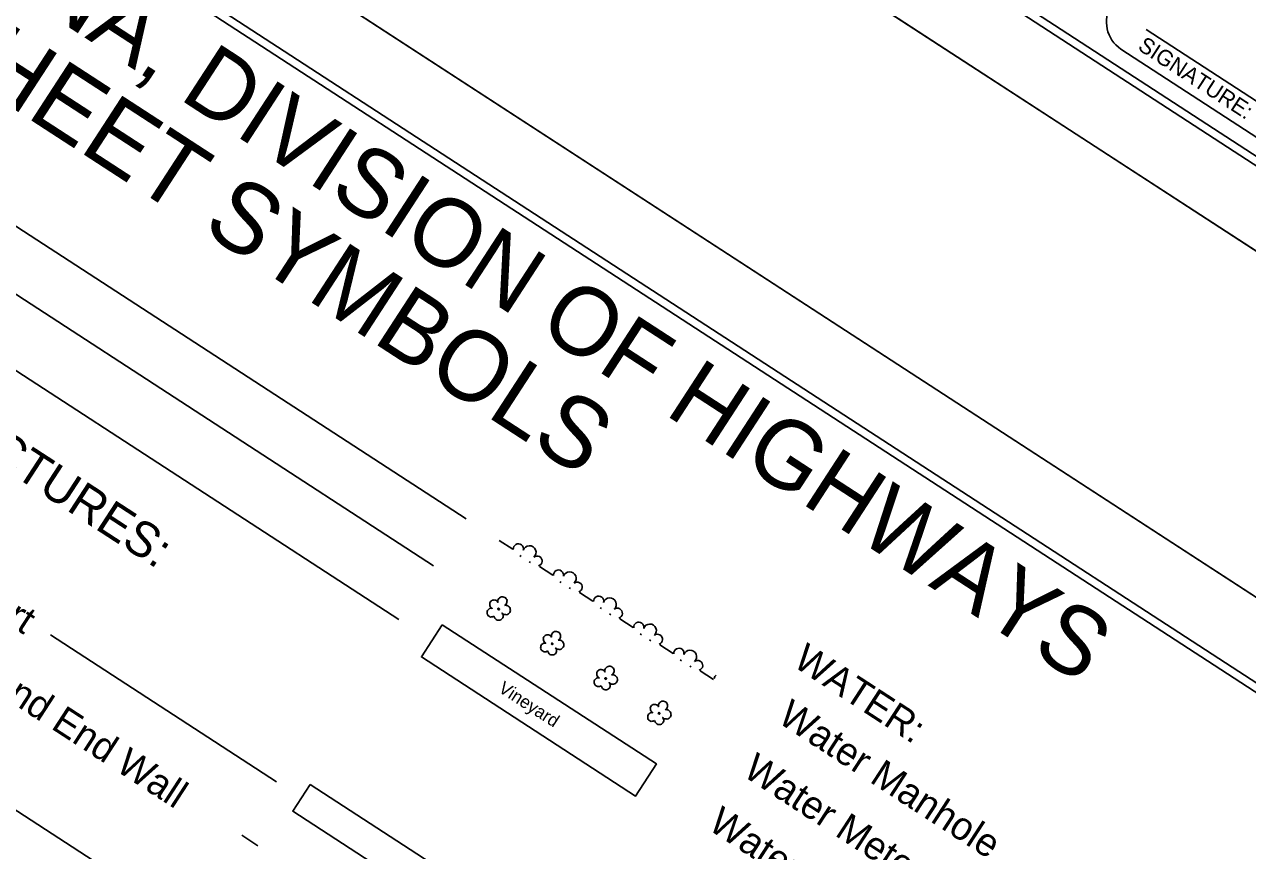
# Model space of a CAD drawing. Extents: x 2291197 to 2302790, y 592892 to 604246.
# Drawn here: x 2296768 to 2298300, y 596869 to 597905 of the extents above; entities that cross this region are included whole.
import ezdxf

# ---------------------------------------------------------------- set-up
doc = ezdxf.new("R2010")
doc.units = 0
for name, color, linetype in [('Prop Shade Light', 7, 'Continuous'), ('Sheet Cutting Line CELL', 7, 'Continuous'), ('Sheet Plot Border Inside CELL', 7, 'Continuous'), ('Sheet Plot Border Outside CELL', 7, 'Continuous'), ('Sheet Symbology CELL', 7, 'Continuous'), ('Sheet Title CELL', 7, 'Continuous')]:
    doc.layers.add(name, color=color, linetype=linetype)

# ---------------------------------------------------------------- blocks, each defined once
blk = doc.blocks.new('PLAN SHEET SYMBOLOGY - New')
at = {"layer": 'Sheet Cutting Line CELL'}
blk.add_line((1439376.56, 921733.15), (1437692.56, 921733.15), dxfattribs=at)
at = {"layer": 'Sheet Plot Border Inside CELL'}
blk.add_lwpolyline([(1437705.56, 920655.6), (1439372.06, 920655.6), (1439372.06, 921710.7), (1437705.56, 921710.7)], close=True, dxfattribs=at)
at = {"layer": 'Sheet Plot Border Outside CELL'}
blk.add_lwpolyline([(1437692.56, 920633.15), (1439376.56, 920633.15), (1439376.56, 921733.15), (1437692.56, 921733.15)], close=True, dxfattribs=at)
at = {"layer": 'Sheet Symbology CELL'}
for p, q in [((1438877.82, 921618.88), (1438696.7, 921618.88)), ((1438890.21, 921618.88), (1438895.21, 921618.88)), ((1438898.16, 921618.38), (1438898.66, 921618.38)), ((1438901.66, 921618.38), (1438902.16, 921618.38)), ((1438905.21, 921618.88), (1438910.21, 921618.88)), ((1438913.16, 921618.38), (1438913.66, 921618.38)), ((1438916.66, 921618.38), (1438917.16, 921618.38)), ((1438920.21, 921618.88), (1438925.21, 921618.88)), ((1438928.16, 921618.38), (1438928.66, 921618.38)), ((1438931.66, 921618.38), (1438932.16, 921618.38)), ((1438935.21, 921618.88), (1438940.21, 921618.88)), ((1438943.16, 921618.38), (1438943.66, 921618.38)), ((1438946.66, 921618.38), (1438947.16, 921618.38)), ((1438950.21, 921618.88), (1438955.21, 921618.88)), ((1438958.16, 921618.38), (1438958.66, 921618.38)), ((1438961.66, 921618.38), (1438962.16, 921618.38)), ((1438965.21, 921618.88), (1438970.21, 921618.88)), ((1438877.26, 921600.96), (1438672.32, 921600.96)), ((1438877.26, 921580.96), (1438672.32, 921580.96)), ((1438872.94, 921517.45), (1438788.52, 921517.45)), ((1438872.94, 921497.45), (1438878.93, 921497.45)), ((1438872.94, 921465.46), (1438744.64, 921465.46))]:
    blk.add_line(p, q, dxfattribs=at)
blk.add_lwpolyline([(1439359.56, 921708.15), (1437859.56, 921708.15), (1437859.56, 920659.17), (1439359.56, 920659.17)], close=True, dxfattribs=at)
for points in [[(1438902.7, 921602.71), (1438902.85, 921603.01), (1438902.9, 921603.31), (1438902.85, 921603.61), (1438902.8, 921603.91), (1438902.65, 921604.16), (1438902.5, 921604.41), (1438902.25, 921604.61), (1438902, 921604.76), (1438901.65, 921604.86), (1438901.4, 921604.86), (1438901.1, 921604.81), (1438900.8, 921604.71), (1438900.55, 921604.56), (1438900.3, 921604.36), (1438900.15, 921604.06), (1438900.05, 921603.81), (1438900, 921603.51), (1438900, 921603.21), (1438900.05, 921602.91), (1438900.2, 921602.66), (1438900.4, 921602.36), (1438900.15, 921602.51), (1438899.85, 921602.56), (1438899.55, 921602.56), (1438899.3, 921602.46), (1438899.05, 921602.36), (1438898.8, 921602.16), (1438898.6, 921601.96), (1438898.45, 921601.71), (1438898.4, 921601.46), (1438898.35, 921601.11), (1438898.4, 921600.86), (1438898.5, 921600.61), (1438898.7, 921600.36), (1438898.85, 921600.16), (1438899.1, 921600.01), (1438899.4, 921599.86), (1438899.65, 921599.81), (1438899.95, 921599.81), (1438899.7, 921599.71), (1438899.45, 921599.51), (1438899.3, 921599.31), (1438899.2, 921599.01), (1438899.1, 921598.71), (1438899.1, 921598.46), (1438899.15, 921598.16), (1438899.3, 921597.91), (1438899.45, 921597.66), (1438899.65, 921597.46), (1438899.9, 921597.31), (1438900.15, 921597.21), (1438900.45, 921597.21), (1438900.75, 921597.21), (1438901, 921597.26), (1438901.25, 921597.46), (1438901.5, 921597.61), (1438901.75, 921598.06)], [(1438922.7, 921602.71), (1438922.85, 921603.01), (1438922.9, 921603.31), (1438922.85, 921603.61), (1438922.8, 921603.91), (1438922.65, 921604.16), (1438922.5, 921604.41), (1438922.25, 921604.61), (1438922, 921604.76), (1438921.65, 921604.86), (1438921.4, 921604.86), (1438921.1, 921604.81), (1438920.8, 921604.71), (1438920.55, 921604.56), (1438920.3, 921604.36), (1438920.15, 921604.06), (1438920.05, 921603.81), (1438920, 921603.51), (1438920, 921603.21), (1438920.05, 921602.91), (1438920.2, 921602.66), (1438920.4, 921602.36), (1438920.15, 921602.51), (1438919.85, 921602.56), (1438919.55, 921602.56), (1438919.3, 921602.46), (1438919.05, 921602.36), (1438918.8, 921602.16), (1438918.6, 921601.96), (1438918.45, 921601.71), (1438918.4, 921601.46), (1438918.35, 921601.11), (1438918.4, 921600.86), (1438918.5, 921600.61), (1438918.7, 921600.36), (1438918.85, 921600.16), (1438919.1, 921600.01), (1438919.4, 921599.86), (1438919.65, 921599.81), (1438919.95, 921599.81), (1438919.7, 921599.71), (1438919.45, 921599.51), (1438919.3, 921599.31), (1438919.2, 921599.01), (1438919.1, 921598.71), (1438919.1, 921598.46), (1438919.15, 921598.16), (1438919.3, 921597.91), (1438919.45, 921597.66), (1438919.65, 921597.46), (1438919.9, 921597.31), (1438920.15, 921597.21), (1438920.45, 921597.21), (1438920.75, 921597.21), (1438921, 921597.26), (1438921.25, 921597.46), (1438921.5, 921597.61), (1438921.75, 921598.06)], [(1438942.7, 921602.71), (1438942.85, 921603.01), (1438942.9, 921603.31), (1438942.85, 921603.61), (1438942.8, 921603.91), (1438942.65, 921604.16), (1438942.5, 921604.41), (1438942.25, 921604.61), (1438942, 921604.76), (1438941.65, 921604.86), (1438941.4, 921604.86), (1438941.1, 921604.81), (1438940.8, 921604.71), (1438940.55, 921604.56), (1438940.3, 921604.36), (1438940.15, 921604.06), (1438940.05, 921603.81), (1438940, 921603.51), (1438940, 921603.21), (1438940.05, 921602.91), (1438940.2, 921602.66), (1438940.4, 921602.36), (1438940.15, 921602.51), (1438939.85, 921602.56), (1438939.55, 921602.56), (1438939.3, 921602.46), (1438939.05, 921602.36), (1438938.8, 921602.16), (1438938.6, 921601.96), (1438938.45, 921601.71), (1438938.4, 921601.46), (1438938.35, 921601.11), (1438938.4, 921600.86), (1438938.5, 921600.61), (1438938.7, 921600.36), (1438938.85, 921600.16), (1438939.1, 921600.01), (1438939.4, 921599.86), (1438939.65, 921599.81), (1438939.95, 921599.81), (1438939.7, 921599.71), (1438939.45, 921599.51), (1438939.3, 921599.31), (1438939.2, 921599.01), (1438939.1, 921598.71), (1438939.1, 921598.46), (1438939.15, 921598.16), (1438939.3, 921597.91), (1438939.45, 921597.66), (1438939.65, 921597.46), (1438939.9, 921597.31), (1438940.15, 921597.21), (1438940.45, 921597.21), (1438940.75, 921597.21), (1438941, 921597.26), (1438941.25, 921597.46), (1438941.5, 921597.61), (1438941.75, 921598.06)], [(1438962.7, 921602.71), (1438962.85, 921603.01), (1438962.9, 921603.31), (1438962.85, 921603.61), (1438962.8, 921603.91), (1438962.65, 921604.16), (1438962.5, 921604.41), (1438962.25, 921604.61), (1438962, 921604.76), (1438961.65, 921604.86), (1438961.4, 921604.86), (1438961.1, 921604.81), (1438960.8, 921604.71), (1438960.55, 921604.56), (1438960.3, 921604.36), (1438960.15, 921604.06), (1438960.05, 921603.81), (1438960, 921603.51), (1438960, 921603.21), (1438960.05, 921602.91), (1438960.2, 921602.66), (1438960.4, 921602.36), (1438960.15, 921602.51), (1438959.85, 921602.56), (1438959.55, 921602.56), (1438959.3, 921602.46), (1438959.05, 921602.36), (1438958.8, 921602.16), (1438958.6, 921601.96), (1438958.45, 921601.71), (1438958.4, 921601.46), (1438958.35, 921601.11), (1438958.4, 921600.86), (1438958.5, 921600.61), (1438958.7, 921600.36), (1438958.85, 921600.16), (1438959.1, 921600.01), (1438959.4, 921599.86), (1438959.65, 921599.81), (1438959.95, 921599.81), (1438959.7, 921599.71), (1438959.45, 921599.51), (1438959.3, 921599.31), (1438959.2, 921599.01), (1438959.1, 921598.71), (1438959.1, 921598.46), (1438959.15, 921598.16), (1438959.3, 921597.91), (1438959.45, 921597.66), (1438959.65, 921597.46), (1438959.9, 921597.31), (1438960.15, 921597.21), (1438960.45, 921597.21), (1438960.75, 921597.21), (1438961, 921597.26), (1438961.25, 921597.46), (1438961.5, 921597.61), (1438961.75, 921598.06)], [(1438901.85, 921600.96), (1438901.7, 921600.96), (1438901.6, 921600.91), (1438901.5, 921600.86), (1438901.5, 921600.71), (1438901.5, 921600.61), (1438901.6, 921600.51), (1438901.75, 921600.51), (1438901.85, 921600.51), (1438901.95, 921600.61), (1438902, 921600.76), (1438901.95, 921600.86), (1438901.85, 921600.96)], [(1438901.75, 921598.06), (1438902.35, 921597.71), (1438902.65, 921597.61), (1438902.95, 921597.56), (1438903.25, 921597.61), (1438903.5, 921597.71), (1438903.75, 921597.86), (1438904, 921598.06), (1438904.15, 921598.31), (1438904.25, 921598.56), (1438904.35, 921598.86), (1438904.3, 921599.16), (1438904.25, 921599.46), (1438904.05, 921599.76), (1438903.9, 921599.96), (1438903.65, 921600.11), (1438903.35, 921600.26), (1438903.65, 921600.21), (1438904, 921600.21), (1438904.25, 921600.31), (1438904.55, 921600.46), (1438904.8, 921600.61), (1438905, 921600.86), (1438905.15, 921601.16), (1438905.2, 921601.46), (1438905.25, 921601.76), (1438905.2, 921602.06), (1438905.1, 921602.36), (1438904.9, 921602.61), (1438904.65, 921602.86), (1438904.4, 921603.01), (1438904.1, 921603.11), (1438903.8, 921603.16), (1438903.5, 921603.16), (1438903.2, 921603.06), (1438902.95, 921602.91), (1438902.7, 921602.71)], [(1438921.85, 921600.96), (1438921.7, 921600.96), (1438921.6, 921600.91), (1438921.5, 921600.86), (1438921.5, 921600.71), (1438921.5, 921600.61), (1438921.6, 921600.51), (1438921.75, 921600.51), (1438921.85, 921600.51), (1438921.95, 921600.61), (1438922, 921600.76), (1438921.95, 921600.86), (1438921.85, 921600.96)], [(1438921.75, 921598.06), (1438922.35, 921597.71), (1438922.65, 921597.61), (1438922.95, 921597.56), (1438923.25, 921597.61), (1438923.5, 921597.71), (1438923.75, 921597.86), (1438924, 921598.06), (1438924.15, 921598.31), (1438924.25, 921598.56), (1438924.35, 921598.86), (1438924.3, 921599.16), (1438924.25, 921599.46), (1438924.05, 921599.76), (1438923.9, 921599.96), (1438923.65, 921600.11), (1438923.35, 921600.26), (1438923.65, 921600.21), (1438924, 921600.21), (1438924.25, 921600.31), (1438924.55, 921600.46), (1438924.8, 921600.61), (1438925, 921600.86), (1438925.15, 921601.16), (1438925.2, 921601.46), (1438925.25, 921601.76), (1438925.2, 921602.06), (1438925.1, 921602.36), (1438924.9, 921602.61), (1438924.65, 921602.86), (1438924.4, 921603.01), (1438924.1, 921603.11), (1438923.8, 921603.16), (1438923.5, 921603.16), (1438923.2, 921603.06), (1438922.95, 921602.91), (1438922.7, 921602.71)], [(1438941.85, 921600.96), (1438941.7, 921600.96), (1438941.6, 921600.91), (1438941.5, 921600.86), (1438941.5, 921600.71), (1438941.5, 921600.61), (1438941.6, 921600.51), (1438941.75, 921600.51), (1438941.85, 921600.51), (1438941.95, 921600.61), (1438942, 921600.76), (1438941.95, 921600.86), (1438941.85, 921600.96)], [(1438941.75, 921598.06), (1438942.35, 921597.71), (1438942.65, 921597.61), (1438942.95, 921597.56), (1438943.25, 921597.61), (1438943.5, 921597.71), (1438943.75, 921597.86), (1438944, 921598.06), (1438944.15, 921598.31), (1438944.25, 921598.56), (1438944.35, 921598.86), (1438944.3, 921599.16), (1438944.25, 921599.46), (1438944.05, 921599.76), (1438943.9, 921599.96), (1438943.65, 921600.11), (1438943.35, 921600.26), (1438943.65, 921600.21), (1438944, 921600.21), (1438944.25, 921600.31), (1438944.55, 921600.46), (1438944.8, 921600.61), (1438945, 921600.86), (1438945.15, 921601.16), (1438945.2, 921601.46), (1438945.25, 921601.76), (1438945.2, 921602.06), (1438945.1, 921602.36), (1438944.9, 921602.61), (1438944.65, 921602.86), (1438944.4, 921603.01), (1438944.1, 921603.11), (1438943.8, 921603.16), (1438943.5, 921603.16), (1438943.2, 921603.06), (1438942.95, 921602.91), (1438942.7, 921602.71)], [(1438961.85, 921600.96), (1438961.7, 921600.96), (1438961.6, 921600.91), (1438961.5, 921600.86), (1438961.5, 921600.71), (1438961.5, 921600.61), (1438961.6, 921600.51), (1438961.75, 921600.51), (1438961.85, 921600.51), (1438961.95, 921600.61), (1438962, 921600.76), (1438961.95, 921600.86), (1438961.85, 921600.96)], [(1438961.75, 921598.06), (1438962.35, 921597.71), (1438962.65, 921597.61), (1438962.95, 921597.56), (1438963.25, 921597.61), (1438963.5, 921597.71), (1438963.75, 921597.86), (1438964, 921598.06), (1438964.15, 921598.31), (1438964.25, 921598.56), (1438964.35, 921598.86), (1438964.3, 921599.16), (1438964.25, 921599.46), (1438964.05, 921599.76), (1438963.9, 921599.96), (1438963.65, 921600.11), (1438963.35, 921600.26), (1438963.65, 921600.21), (1438964, 921600.21), (1438964.25, 921600.31), (1438964.55, 921600.46), (1438964.8, 921600.61), (1438965, 921600.86), (1438965.15, 921601.16), (1438965.2, 921601.46), (1438965.25, 921601.76), (1438965.2, 921602.06), (1438965.1, 921602.36), (1438964.9, 921602.61), (1438964.65, 921602.86), (1438964.4, 921603.01), (1438964.1, 921603.11), (1438963.8, 921603.16), (1438963.5, 921603.16), (1438963.2, 921603.06), (1438962.95, 921602.91), (1438962.7, 921602.71)], [(1438889.65, 921586.96), (1438969.65, 921586.96), (1438969.65, 921574.96), (1438889.65, 921574.96), (1438889.65, 921586.96)], [(1438882.24, 921522.45), (1438964.74, 921522.45), (1438964.74, 921512.45), (1438882.24, 921512.45), (1438882.24, 921522.45)]]:
    blk.add_lwpolyline(points, dxfattribs=at)
for centre, radius, start, end in [((1438896.66, 921619.9), 1.58, 18.435, 219.2315), ((1438900.16, 921620.9), 2.06, 345.9638, 194.0362), ((1438903.66, 921619.9), 1.58, 320.7685, 161.5651), ((1438911.66, 921619.9), 1.58, 18.435, 219.2315), ((1438915.16, 921620.9), 2.06, 345.9638, 194.0362), ((1438918.66, 921619.9), 1.58, 320.7685, 161.5651), ((1438926.66, 921619.9), 1.58, 18.435, 219.2315), ((1438930.16, 921620.9), 2.06, 345.9638, 194.0362), ((1438933.66, 921619.9), 1.58, 320.7685, 161.5651), ((1438941.66, 921619.9), 1.58, 18.435, 219.2315), ((1438945.16, 921620.9), 2.06, 345.9638, 194.0362), ((1438948.66, 921619.9), 1.58, 320.7685, 161.5651), ((1438956.66, 921619.9), 1.58, 18.435, 219.2315), ((1438960.16, 921620.9), 2.06, 345.9638, 194.0362), ((1438963.66, 921619.9), 1.58, 320.7685, 161.5651), ((1438971.66, 921619.9), 1.58, 156.251, 203.749)]:
    blk.add_arc(centre, radius, start, end, dxfattribs=at)
for s, height, p in [('STATE OF NORTH CAROLINA, DIVISION OF HIGHWAYS', 21.419, (1438310.12, 921680.19)), ('CONVENTIONAL  PLAN SHEET SYMBOLS', 22.0323, (1438318.25, 921649.31)), ('WATER:', 8.75, (1438988.35, 921635.98)), ('Water Manhole', 8.75, (1438993.92, 921618.6)), ('Water Meter', 8.75, (1438993.92, 921598.6)), ('Water Valve', 8.75, (1438993.92, 921578.6)), ('EXISTING STRUCTURES:', 11, (1438627.98, 921552.9)), ('Bridge, Tunnel or Box Culvert', 8.75, (1438627.98, 921512.9)), ('Bridge Wing Wall, Head Wall and End Wall', 8.75, (1438627.98, 921492.9))]:
    blk.add_text(s, height=height, dxfattribs=at).set_placement(p)
blk.add_text('Vineyard', height=4, rotation=0, dxfattribs=at).set_placement((1438915.47, 921578.96))

msp = doc.modelspace()

# ---------------------------------------------------------------- linework, layer by layer
at = {"layer": 'Sheet Cutting Line CELL'}
for p, q in [((2293793.6, 600557.1), (2299441.2, 596885.8)), ((2299242.9, 596580.9), (2293595.3, 600252.2))]:
    msp.add_line(p, q, dxfattribs=at)
at = {"layer": 'Sheet Plot Border Inside CELL'}
msp.add_lwpolyline([(2293886.1, 600604), (2299475, 596970.9), (2301775.2, 600509.4), (2296186.3, 604142.5)], close=True, dxfattribs=at)
at = {"layer": 'Sheet Plot Border Outside CELL'}
msp.add_lwpolyline([(2301839.2, 600574.8), (2296191.6, 604246.1), (2293793.6, 600557.1), (2299441.2, 596885.8)], close=True, dxfattribs=at)
at = {"layer": 'Sheet Title CELL'}
msp.add_line((2298173.1, 597898.4), (2298647.6, 597589.8), dxfattribs=at)
for points in [[(2294441.6, 600255), (2299405.1, 597028.5)], [(2298141.6, 597873.7), (2298811.6, 597438.2)]]:
    msp.add_lwpolyline(points, dxfattribs=at)
msp.add_arc((2298163.5, 597907.4), 40, 146.9737, 236.9737, dxfattribs=at)

# ---------------------------------------------------------------- block references
at = {"layer": 'Prop Shade Light', "xscale": 4, "yscale": 3.9999999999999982, "rotation": -33.02629958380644}
msp.add_blockref('PLAN SHEET SYMBOLOGY - New', (-4537434.8, 643359.8), dxfattribs=at)

# ---------------------------------------------------------------- texts
at = {"layer": 'Sheet Title CELL'}
msp.add_text('SIGNATURE:', height=20, rotation=326.9737, dxfattribs=at).set_placement((2298161.5, 597873.9))

doc.saveas('drawing.dxf')
